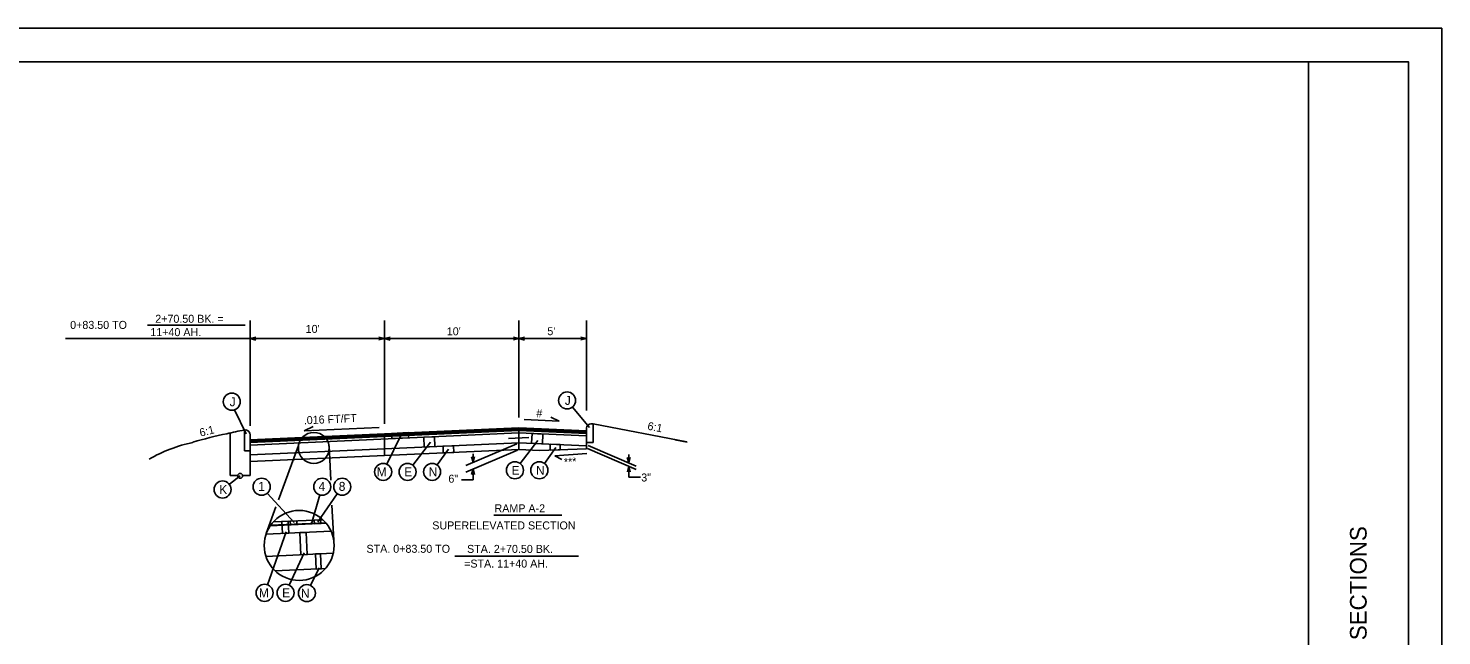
# Model space of a CAD drawing. Extents: x -196 to 300, y -73 to 205.
# Drawn here: x 64 to 170, y 64.5 to 110 of the extents above; entities that cross this region are included whole.
import ezdxf

# ---------------------------------------------------------------- set-up
doc = ezdxf.new("R2010")
doc.units = 0
for name, color, linetype in [('Level 4', 7, 'Continuous'), ('Level 59', 7, 'Continuous'), ('Level 6', 7, 'Continuous'), ('Level 7', 7, 'Continuous'), ('SH_Border', 7, 'Continuous'), ('SH_Cut_Line', 7, 'Continuous'), ('SH_Data', 7, 'Continuous')]:
    doc.layers.add(name, color=color, linetype=linetype)

msp = doc.modelspace()

# ---------------------------------------------------------------- linework, layer by layer
at = {"layer": 'Level 4'}
for p, q in [((80.65, 80.22), (80.65, 88.12)), ((90.73, 88.12), (90.73, 80.37)), ((100.81, 80.84), (100.81, 88.12)), ((105.87, 81.36), (105.87, 88.12)), ((72.95, 87.75), (80.28, 87.75)), ((80.65, 86.76), (66.81, 86.76)), ((80.65, 86.76), (90.73, 86.76)), ((90.73, 86.76), (100.81, 86.76)), ((100.81, 86.76), (105.87, 86.76)), ((105.87, 81.36), (105.87, 84.94)), ((101.19, 80.69), (103.83, 80.58)), ((103.83, 80.58), (103.19, 80.88)), ((84.7, 79.85), (85.37, 80.17)), ((90.33, 80.1), (84.7, 79.85)), ((100.65, 78.88), (96.82, 77.25)), ((105.96, 78.51), (109.6, 76.96)), ((105.99, 78.74), (109.59, 77.2)), ((100.69, 78.4), (96.82, 76.75)), ((97.37, 77.49), (97.37, 78.12)), ((103.5, 77.97), (105.9, 78.14)), ((103.5, 77.97), (104.02, 77.7)), ((109.04, 77.44), (109.04, 78.07)), ((97.37, 76.18), (97.37, 76.99)), ((109.05, 76.38), (109.05, 77.19)), ((109.92, 76.38), (109.05, 76.38)), ((96.5, 76.18), (97.37, 76.18)), ((98.92, 73.54), (104.02, 73.54)), ((96, 70.46), (105.27, 70.46))]:
    msp.add_line(p, q, dxfattribs=at)
for points in [[(81.07, 86.64), (80.65, 86.76), (81.07, 86.87)], [(90.31, 86.87), (90.73, 86.76), (90.31, 86.65)], [(91.15, 86.64), (90.73, 86.76), (91.15, 86.87)], [(100.39, 86.87), (100.81, 86.76), (100.39, 86.65)], [(101.23, 86.64), (100.81, 86.76), (101.23, 86.87)], [(105.45, 86.87), (105.87, 86.76), (105.45, 86.65)], [(97.49, 77.91), (97.37, 77.49), (97.26, 77.91)], [(108.92, 77.86), (109.04, 77.44), (109.15, 77.86)], [(97.26, 76.57), (97.37, 76.99), (97.48, 76.57)], [(109.16, 76.77), (109.05, 77.19), (108.94, 76.77)]]:
    msp.add_lwpolyline(points, dxfattribs=at)
at = {"layer": 'Level 59'}
for p, q in [((104.82, 81.63), (106.1, 80.1)), ((79.48, 81.42), (80.37, 79.62)), ((91.94, 79.45), (90.91, 77.35)), ((94.19, 78.99), (92.86, 77.28)), ((95.53, 78.48), (94.67, 77.29)), ((102.23, 79.11), (100.9, 77.39)), ((103.57, 78.6), (102.72, 77.41)), ((79.91, 76.47), (79.1, 75.84)), ((81.94, 75.18), (83.95, 72.98)), ((85.88, 75.04), (85.26, 72.87)), ((87.19, 75.13), (85.72, 73.02)), ((81.96, 68.32), (83.36, 72.28)), ((83.58, 68.29), (84.7, 70.7)), ((85.18, 68.27), (85.82, 69.59))]:
    msp.add_line(p, q, dxfattribs=at)
for points in [[(91.28, 79.26), (92.53, 79.31), (92.51, 79.71), (91.27, 79.65)], [(101.76, 78.91), (102.57, 78.87), (102.61, 79.6), (101.79, 79.64)], [(93.7, 78.63), (94.51, 78.67), (94.48, 79.4), (93.67, 79.36)], [(95.14, 78.2), (95.93, 78.23), (95.91, 78.73), (95.12, 78.7)], [(103.15, 78.4), (103.16, 78.85), (103.89, 78.82), (103.89, 78.82), (103.89, 78.43)], [(85.47, 72.88), (85.96, 72.9), (85.94, 73.18), (85.46, 73.16)], [(83.07, 72.15), (83.55, 72.17), (83.51, 73.07), (83.02, 73.05)], [(83.67, 72.8), (84.15, 72.82), (84.15, 73.1), (83.66, 73.08)], [(84.45, 70.56), (84.94, 70.58), (84.86, 72.24), (84.37, 72.22)], [(85.61, 69.49), (85.99, 69.5), (85.94, 70.64), (85.56, 70.62)]]:
    msp.add_lwpolyline(points, close=True, dxfattribs=at)
for centre in [(79.28, 82.03), (104.42, 82.12), (90.63, 76.77), (92.46, 76.77), (94.3, 76.77), (100.51, 76.89), (102.34, 76.89), (78.59, 75.45), (81.52, 75.66), (86.06, 75.66), (87.56, 75.66), (81.74, 67.71), (83.31, 67.71), (84.91, 67.69)]:
    msp.add_circle(centre, 0.639, dxfattribs=at)
at = {"layer": 'Level 6'}
for p, q in [((79.15, 79.69), (79.15, 76.49)), ((80.23, 79.91), (80.23, 78.35)), ((80.23, 79.91), (80.32, 79.91)), ((80.65, 79.18), (100.81, 80.08)), ((80.65, 79.07), (100.81, 79.98)), ((80.65, 78.78), (100.81, 79.69)), ((80.65, 79.55), (80.65, 76.49)), ((100.81, 80.08), (100.81, 78.45)), ((105.87, 79.75), (100.81, 79.98)), ((105.86, 79.46), (100.81, 79.69)), ((105.87, 78.5), (105.87, 80.06)), ((106.37, 80.38), (106.21, 80.38)), ((106.37, 80.38), (113.39, 79.01)), ((106.37, 78.97), (106.37, 80.38)), ((80.65, 78.05), (100.81, 78.95)), ((80.65, 77.55), (100.81, 78.45)), ((90.73, 79.47), (90.73, 78)), ((100.02, 79.28), (101.56, 79.34)), ((105.87, 78.72), (100.81, 78.95)), ((100.81, 78.44), (102.34, 78.37)), ((102.34, 78.37), (105.87, 78.5)), ((105.87, 78.97), (106.37, 78.97)), ((112.51, 79.17), (113.42, 78.99)), ((80.23, 78.35), (80.65, 78.35)), ((79.15, 76.49), (79.72, 76.49)), ((80.09, 76.49), (80.65, 76.49)), ((82.39, 73.02), (84.85, 73.13)), ((81.84, 72.1), (86.73, 72.32)), ((82.19, 72.78), (86.32, 72.96)), ((81.83, 70.44), (86.88, 70.67)), ((82.53, 69.35), (86.29, 69.52))]:
    msp.add_line(p, q, dxfattribs=at)
msp.add_circle((79.91, 76.47), 0.183, dxfattribs=at)
for centre, radius, start, end in [((84.79, 50.67), 29.55, 101.4847, 106.5755), ((83.39, 61.68), 18.5, 99.8448, 104.0425), ((80.26, 79.52), 0.4, 4.5012, 80.3635), ((106.25, 79.99), 0.387, 96.0275, 169.6786), ((78.51, 68.42), 10.77, 101.4936, 120.3111)]:
    msp.add_arc(centre, radius, start, end, dxfattribs=at)
at = {"layer": 'Level 7'}
for p, q in [((80.65, 79.18), (100.81, 80.08)), ((80.65, 79.05), (100.81, 79.96)), ((80.65, 78.97), (100.81, 79.87)), ((100.81, 80.08), (105.87, 79.85)), ((105.87, 79.73), (100.81, 79.96)), ((105.87, 79.65), (100.81, 79.87)), ((82.79, 74.68), (84.28, 78.74)), ((86.7, 76.16), (86.58, 78.72)), ((86.92, 71.66), (86.79, 74.28)), ((81.86, 72.15), (82.59, 74.15)), ((82.38, 73.02), (86.1, 73.19)), ((82.15, 72.73), (86.36, 72.92))]:
    msp.add_line(p, q, dxfattribs=at)
for centre, radius in [((85.43, 78.57), 1.16), ((84.33, 71.26), 2.62)]:
    msp.add_circle(centre, radius, dxfattribs=at)
at = {"layer": 'SH_Border'}
msp.add_line((160, 2.5), (160, 107.5), dxfattribs=at)
msp.add_lwpolyline([(7.5, 107.5), (167.5, 107.5), (167.5, 2.5), (7.5, 2.5)], close=True, dxfattribs=at)
at = {"layer": 'SH_Cut_Line'}
msp.add_lwpolyline([(0, 0), (170, 0), (170, 110), (0, 110)], close=True, dxfattribs=at)

# ---------------------------------------------------------------- texts
at = {"layer": 'Level 4'}
for s, p in [('0+83.50 TO', (67.16, 87.48)), ('2+70.50 BK. =', (73.54, 87.94)), ('11+40 AH.', (73.17, 86.94)), ("10'", (84.82, 87.18)), ("10'", (95.4, 87)), ("5'", (102.94, 87.01)), ('#', (102.11, 80.85)), ('6"', (95.52, 75.96)), ('3"', (109.98, 76.05)), ('RAMP A-2', (98.98, 73.74)), ('SUPERELEVATED SECTION', (94.31, 72.46)), ('STA. 0+83.50 TO', (89.38, 70.71)), ('STA. 2+70.50 BK. ', (96.92, 70.7)), ('=STA. 11+40 AH.', (96.7, 69.6))]:
    msp.add_text(s, height=0.6, dxfattribs=at).set_placement(p)
for s, rotation, p in [('.016 FT/FT', 2.5707, (84.69, 80.33)), ('6:1', 13.9187, (76.94, 79.4)), ('6:1', 348.9796, (110.41, 79.94)), ('***', 4.0774, (104.21, 77.2))]:
    msp.add_text(s, height=0.6, rotation=rotation, dxfattribs=at).set_placement(p)
at = {"layer": 'Level 59'}
for s, p in [('J', (79.12, 81.69)), ('J', (104.25, 81.79)), ('M', (90.15, 76.44)), ('E', (92.21, 76.44)), ('N', (94.04, 76.44)), ('E', (100.26, 76.55)), ('N', (102.09, 76.55)), ('K', (78.34, 75.11)), ('1', (81.26, 75.35)), ('4', (85.79, 75.35)), ('8', (87.3, 75.35)), ('M', (81.31, 67.37)), ('E', (83.05, 67.37)), ('N', (84.46, 67.34))]:
    msp.add_text(s, height=0.67, dxfattribs=at).set_placement(p)
at = {"layer": 'SH_Data'}
msp.add_text('TYPICAL SECTIONS', height=1.25, rotation=90, dxfattribs=at).set_placement((164.37, 56.73))

doc.saveas('drawing.dxf')
